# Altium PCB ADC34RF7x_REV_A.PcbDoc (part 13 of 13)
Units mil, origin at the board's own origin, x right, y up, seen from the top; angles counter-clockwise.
Board outline 6250 x 2716.54 mil, 18 copper layers (Top Layer, L2 GND, L3 PWR, L4 GND, L5 PWR/SIG, L6 GND, L7 SIGNAL, L8 GND, L9 GND, L10 SIGNAL, L11 GND, L12 SIGNAL, L13 GND, L14 PWR, L15 GND, L16 PWR/SIG, L16 GND, Bottom Layer), stack 95.314 mil thick; 668 components, 786 nets, 3150 pads, 2020 vias.
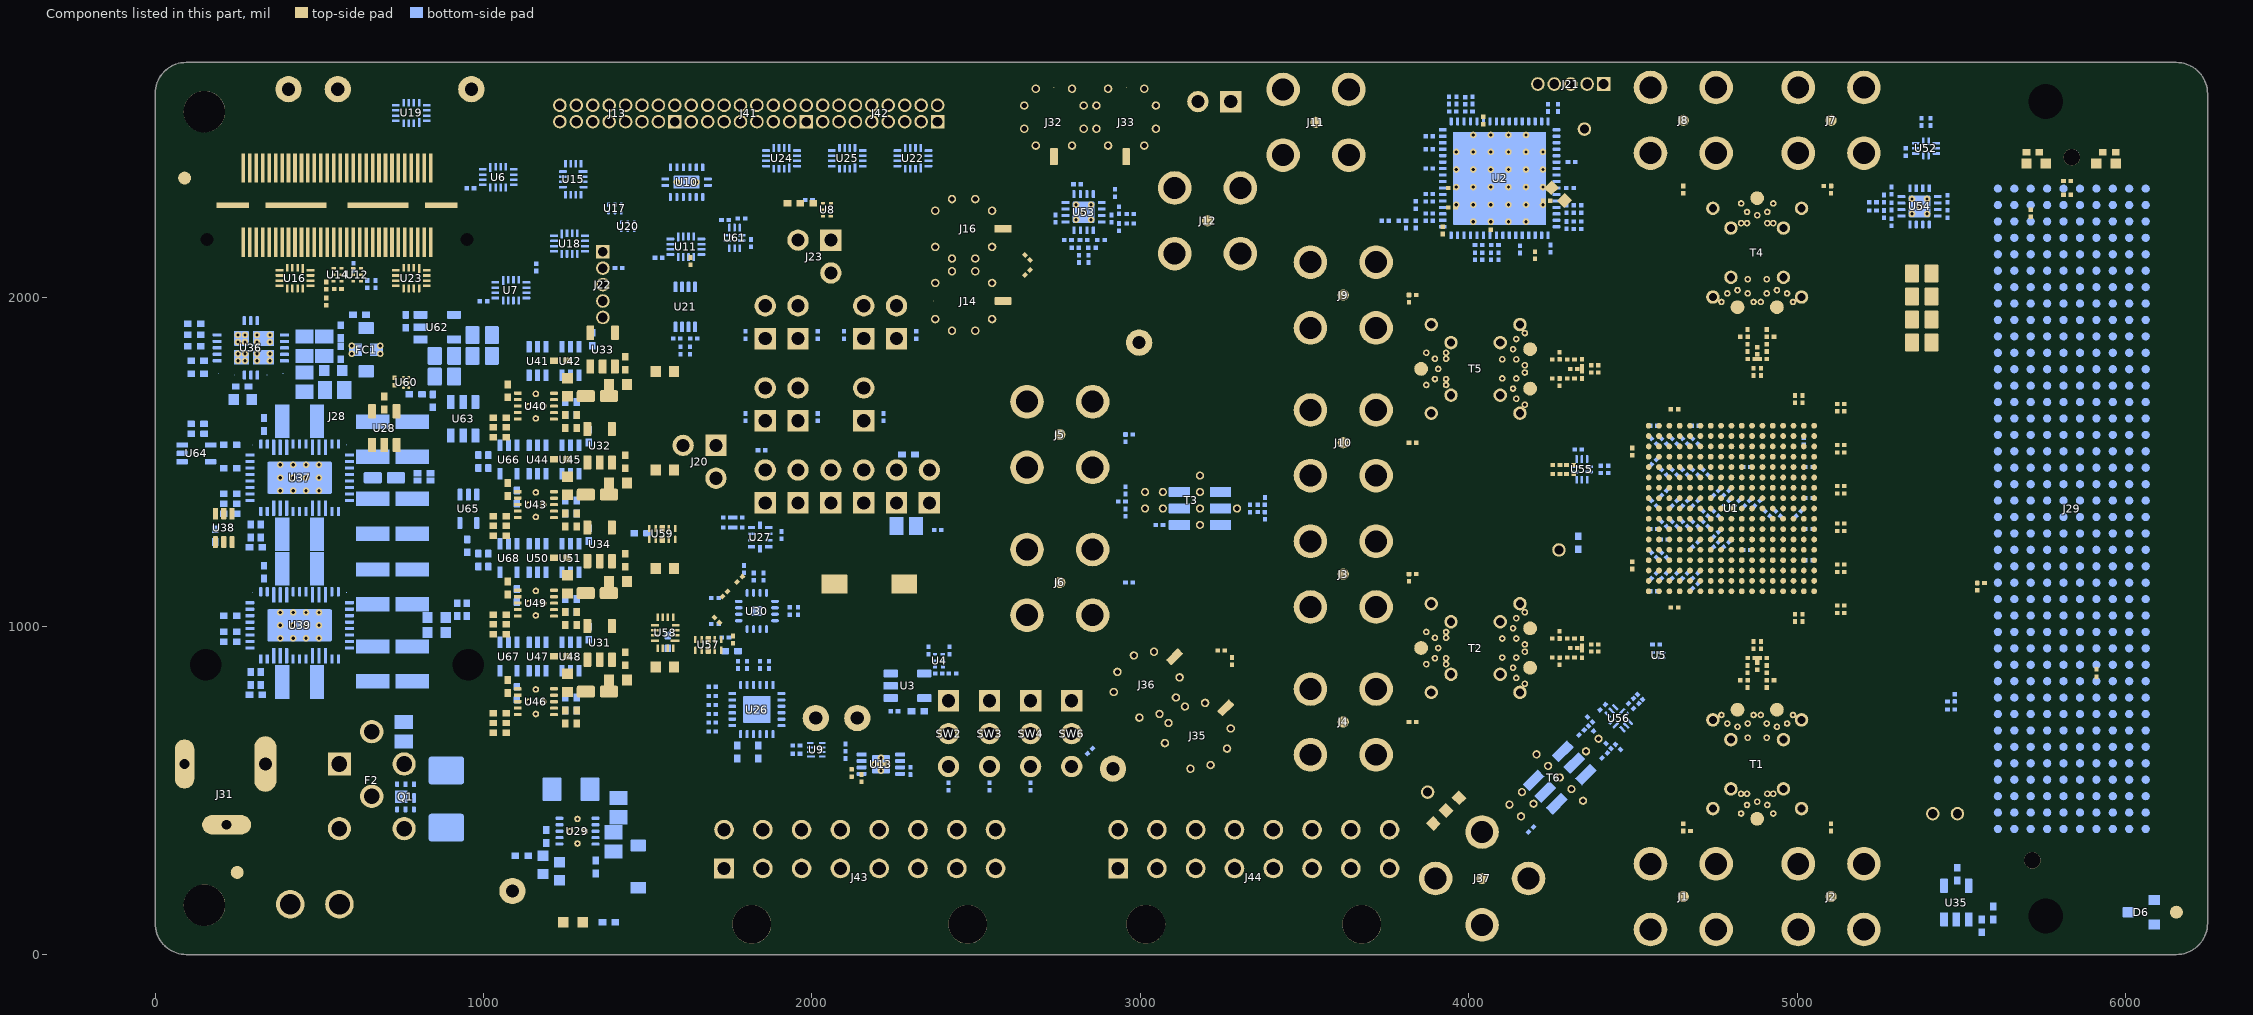
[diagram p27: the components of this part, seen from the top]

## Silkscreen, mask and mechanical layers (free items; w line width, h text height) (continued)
Drill Drawing:
  drawing of 189 lines, arcs and shapes, not listed
  text "Symbol" at 384.42,10966 h48
  text "Count" at 732.34,10966 h48
  text "Hole Size" at 1178.89,10966 h48
  text "Plated" at 1952,10966 h48
  text "Hole Type" at 2299.92,10966 h48
  text "Drill Layer Pair" at 2799.79,10966 h48
  text "Via/Pad" at 3806.15,10966 h48
  text "Pad Shape" at 4210.05,10966 h48
  text "Template" at 4717.92,10966 h48
  text "Description" at 5524.35,10966 h48
  text "Hole Tolerance (+)" at 6104.19,10966 h48
  text "Hole Tolerance (-)" at 7003.93,10966 h48
  text "1" at 732.34,10866 h40
  text "39.76mil (1.010mm)" at 1178.89,10866 h40
  text "PTH" at 1952,10866 h40
  text "Slot" at 2299.92,10866 h40
  text "Top Layer - Bottom Layer" at 2799.79,10866 h40
  text "Pad" at 3806.15,10866 h40
  text "Rounded" at 4210.05,10866 h40
  text "r430_170h101_356r85" at 4717.92,10866 h40
  text "2" at 732.34,10766 h40
  text "29.92mil (0.760mm)" at 1178.89,10766 h40
  text "PTH" at 1952,10766 h40
  text "Slot" at 2299.92,10766 h40
  text "Top Layer - Bottom Layer" at 2799.79,10766 h40
  text "Pad" at 3806.15,10766 h40
  text "Rounded" at 4210.05,10766 h40
  text "r380_150h76_305r75" at 4717.92,10766 h40
  text "A" at 362.74,10756.01 h44.44
  text "2" at 732.34,10666 h40
  text "40.16mil (1.020mm)" at 1178.89,10666 h40
  text "NPTH" at 1952,10666 h40
  text "Round" at 2299.92,10666 h40
  text "Top Layer - Bottom Layer" at 2799.79,10666 h40
  text "Pad" at 3806.15,10666 h40
  text "Rounded" at 4210.05,10666 h40
  text "c0hn102" at 4717.92,10666 h40
  text "2" at 732.34,10566 h40
  text "50.00mil (1.270mm)" at 1178.89,10566 h40
  text "NPTH" at 1952,10566 h40
  text "Round" at 2299.92,10566 h40
  text "Top Layer - Bottom Layer" at 2799.79,10566 h40
  text "Pad" at 3806.15,10566 h40
  text "Rounded" at 4210.05,10566 h40
  text "c127hn127" at 4717.92,10566 h40
  text "2" at 732.34,10466 h40
  text "63.00mil (1.600mm)" at 1178.89,10466 h40
  text "PTH" at 1952,10466 h40
  text "Round" at 2299.92,10466 h40
  text "Top Layer - Bottom Layer" at 2799.79,10466 h40
  text "Pad" at 3806.15,10466 h40
  text "Rounded" at 4210.05,10466 h40
  text "c221h160" at 4717.92,10466 h40
  text "2" at 732.34,10366 h40
  text "96.46mil (2.450mm)" at 1178.89,10366 h40
  text "NPTH" at 1952,10366 h40
  text "Round" at 2299.92,10366 h40
  text "Top Layer - Bottom Layer" at 2799.79,10366 h40
  text "Pad" at 3806.15,10366 h40
  text "Rounded" at 4210.05,10366 h40
  text "c200hn245" at 4717.92,10366 h40
  text "2" at 732.34,10266 h40
  text "105.91mil (2.690mm)" at 1178.89,10266 h40
  text "NPTH" at 1952,10266 h40
  text "Round" at 2299.92,10266 h40
  text "Top Layer - Bottom Layer" at 2799.79,10266 h40
  text "Pad" at 3806.15,10266 h40
  text "Rounded" at 4210.05,10266 h40
  text "c-127hn269" at 4717.92,10266 h40
  text "2" at 732.34,10166 h40
  text "125.98mil (3.200mm)" at 1178.89,10166 h40
  text "NPTH" at 1952,10166 h40
  text "Round" at 2299.92,10166 h40
  text "Top Layer - Bottom Layer" at 2799.79,10166 h40
  text "Pad" at 3806.15,10166 h40
  text "Rounded" at 4210.05,10166 h40
  text "c320hn320m320p0" at 4717.92,10166 h40
  text "4" at 732.34,10066 h40
  text "118.11mil (3.000mm)" at 1178.89,10066 h40
  text "NPTH" at 1952,10066 h40
  text "Round" at 2299.92,10066 h40
  text "Top Layer - Bottom Layer" at 2799.79,10066 h40
  text "Pad" at 3806.15,10066 h40
  text "Rounded" at 4210.05,10066 h40
  text "c300hn300m315" at 4717.92,10066 h40
  text "5" at 732.34,9966 h40
  text "28.00mil (0.711mm)" at 1178.89,9966 h40
  text "PTH" at 1952,9966 h40
  text "Round" at 2299.92,9966 h40
  text "Top Layer - Bottom Layer" at 2799.79,9966 h40
  text "Pad" at 3806.15,9966 h40
  text "Rounded" at 4210.05,9966 h40
  text "c104h71" at 4717.92,9966 h40
  text "6" at 732.34,9866 h40
  text "47.24mil (1.200mm)" at 1178.89,9866 h40
  text "PTH" at 1952,9866 h40
  text "Round" at 2299.92,9866 h40
  text "Top Layer - Bottom Layer" at 2799.79,9866 h40
  text "Pad" at 3806.15,9866 h40
  text "(Mixed)" at 4210.05,9866 h40
  text "(Mixed)" at 4717.92,9866 h40
  text "B" at 362.74,9856.01 h44.44
  text "20" at 732.34,9766 h40
  text "15.00mil (0.381mm)" at 1178.89,9766 h40
  text "PTH" at 1952,9766 h40
  text "Round" at 2299.92,9766 h40
  text "Top Layer - Bottom Layer" at 2799.79,9766 h40
  text "Pad" at 3806.15,9766 h40
  text "Rounded" at 4210.05,9766 h40
  text "c64h38m0mx0" at 4717.92,9766 h40
  text "32" at 732.34,9666 h40
  text "25.00mil (0.635mm)" at 1178.89,9666 h40
  text "PTH" at 1952,9666 h40
  text "Round" at 2299.92,9666 h40
  text "Top Layer - Bottom Layer" at 2799.79,9666 h40
  text "Pad" at 3806.15,9666 h40
  text "Rounded" at 4210.05,9666 h40
  text "c104h64m104mx0" at 4717.92,9666 h40
  text "D" at 362.74,9656.01 h44.44
  text "32" at 732.34,9566 h40
  text "40.16mil (1.020mm)" at 1178.89,9566 h40
  text "PTH" at 1952,9566 h40
  text "Round" at 2299.92,9566 h40
  text "Top Layer - Bottom Layer" at 2799.79,9566 h40
  text "Pad" at 3806.15,9566 h40
  text "Rounded" at 4210.05,9566 h40
  text "(Mixed)" at 4717.92,9566 h40
  text "48" at 732.34,9466 h40
  text "15.75mil (0.400mm)" at 1178.89,9466 h40
  text "PTH" at 1952,9466 h40
  text "Round" at 2299.92,9466 h40
  text "Top Layer - Bottom Layer" at 2799.79,9466 h40
  text "Pad" at 3806.15,9466 h40
  text "Rounded" at 4210.05,9466 h40
  text "c65h40m0mx0" at 4717.92,9466 h40
  text "52" at 732.34,9366 h40
  text "66.93mil (1.700mm)" at 1178.89,9366 h40
  text "PTH" at 1952,9366 h40
  text "Round" at 2299.92,9366 h40
  text "Top Layer - Bottom Layer" at 2799.79,9366 h40
  text "Pad" at 3806.15,9366 h40
  text "Rounded" at 4210.05,9366 h40
  text "c260h170m260p0" at 4717.92,9366 h40
  text "54" at 732.34,9266 h40
  text "40.00mil (1.016mm)" at 1178.89,9266 h40
  text "PTH" at 1952,9266 h40
  text "Round" at 2299.92,9266 h40
  text "Top Layer - Bottom Layer" at 2799.79,9266 h40
  text "Pad" at 3806.15,9266 h40
  text "(Mixed)" at 4210.05,9266 h40
  text "(Mixed)" at 4717.92,9266 h40
  text "58" at 732.34,9166 h40
  text "29.53mil (0.750mm)" at 1178.89,9166 h40
  text "PTH" at 1952,9166 h40
  text "Round" at 2299.92,9166 h40
  text "Top Layer - Bottom Layer" at 2799.79,9166 h40
  text "Pad" at 3806.15,9166 h40
  text "(Mixed)" at 4210.05,9166 h40
  text "(Mixed)" at 4717.92,9166 h40
  text "C" at 362.74,9156.01 h44.44
  text "59" at 732.34,9066 h40
  text "8.00mil (0.203mm)" at 1178.89,9066 h40
  text "PTH" at 1952,9066 h40
  text "Round" at 2299.92,9066 h40
  text "Top Layer - Bottom Layer" at 2799.79,9066 h40
  text "Via" at 3806.15,9066 h40
  text "Rounded" at 4210.05,9066 h40
  text "(Mixed)" at 4717.92,9066 h40
  text "168" at 732.34,8966 h40
  text "12.00mil (0.305mm)" at 1178.89,8966 h40
  text "PTH" at 1952,8966 h40
  text "Round" at 2299.92,8966 h40
  text "Top Layer - Bottom Layer" at 2799.79,8966 h40
  text "Via" at 3806.15,8966 h40
  text "Rounded" at 4210.05,8966 h40
  text "v61h30m0mx0" at 4717.92,8966 h40
  text "F" at 362.74,8956.01 h44.44
  text "1990" at 732.34,8866 h40
  text "10.00mil (0.254mm)" at 1178.89,8866 h40
  text "PTH" at 1952,8866 h40
  text "Round" at 2299.92,8866 h40
  text "Top Layer - Bottom Layer" at 2799.79,8866 h40
  text "(Mixed)" at 3806.15,8866 h40
  text "Rounded" at 4210.05,8866 h40
  text "(Mixed)" at 4717.92,8866 h40
  text "E" at 362.74,8856.01 h44.44
  text "2543 Total" at 732.34,8766 h40
  text "Slot definitions :" at 384.42,8662.68 h40
  text "Routed Path Length" at 1082.22,8662.68 h40
  text "= Calculated from tool start centre position to tool end centre position." at 1826.66,8662.68 h40
  text "Hole Length" at 1082.22,8589.37 h40
  text "= Routed Path Length + Tool Size = Slot length as defined in the PCB layout" at 1553.42,8589.37 h40
  text ".Layer_Name" at 577,-858.49 h60
M17 Embedded Cavity:
  text ".Layer_Name" at 577,-858.49 h60
M18 Embedded Assembly:
  text ".Layer_Name" at 577,-858.49 h60
M19 Embedded Keepout:
  text ".Layer_Name" at 567,-858.49 h60
Dimensions:
  lines w6: 3608.06,738.29 3618.06,708.29 ; 3608.06,1128.29 3618.06,1158.29 ; 3608.06,1188.29 3618.06,1158.29 ; 3608.06,1528.27 3618.06,1558.27 ; 3608.06,1588.27 3618.06,1558.27 ; 3608.06,1978.27 3618.06,2008.27 ; 3612.06,708.29 3624.06,708.29 ; 3612.06,2008.27 3624.06,2008.27 ; 3618.06,877.3 3618.06,708.29 ; 3618.06,989.28 3618.06,1158.29 ; 3618.06,1244.81 3618.06,1158.29 ; 3618.06,1471.75 3618.06,1558.27 ; 3618.06,1727.28 3618.06,1558.27 ; 3618.06,1839.26 3618.06,2008.27 ; 3628.06,738.29 3618.06,708.29 ; 3628.06,1128.29 3618.06,1158.29 ; 3628.06,1188.29 3618.06,1158.29 ; 3628.06,1528.27 3618.06,1558.27 ; 3628.06,1588.27 3618.06,1558.27 ; 3628.06,1978.27 3618.06,2008.27 ; 4653.52,170.33 4653.52,182.33 ; 4653.54,2534.21 4653.54,2546.21 ; 4683.52,166.33 4653.52,176.33 ; 4683.52,186.33 4653.52,176.33 ; 4683.54,2530.21 4653.54,2540.21 ; 4683.54,2550.21 4653.54,2540.21 ; 4822.53,176.33 4653.52,176.33 ; 4822.56,2540.21 4653.54,2540.21 ; 4934.51,176.33 5103.52,176.33 ; 4934.53,2540.21 5103.54,2540.21 ; 5073.52,166.33 5103.52,176.33 ; 5073.52,186.33 5103.52,176.33 ; 5073.54,2530.21 5103.54,2540.21 ; 5073.54,2550.21 5103.54,2540.21 ; 5103.52,170.33 5103.52,182.33 ; 5103.54,2534.21 5103.54,2546.21 ; 3612.06,1158.29 3624.06,1158.29 3612.06,1158.29 ; 3612.06,1558.27 3624.06,1558.27 3612.06,1558.27
  text "450" at 4832.56,2519.21 h30
  text "450" at 3639.06,1737.28 h30 r90
  text "399.978" at 3639.06,1254.81 h30 r90
  text "450" at 3639.06,887.3 h30 r90
  text "450" at 4832.53,155.33 h30

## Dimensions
0,2716.54 to 0,0 on M2 Board Dimensions
0,-400 to 1000,-400 on M2 Board Dimensions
